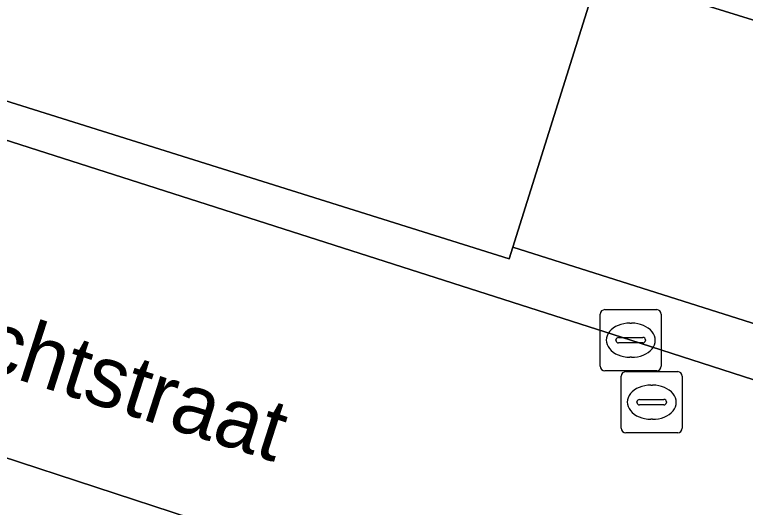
# Model space of a CAD drawing. Extents: x 160675 to 161153, y 383241 to 383714.
# Drawn here: x 160899.69 to 160911.66, y 383397.88 to 383405.95 of the extents above; entities that cross this region are included whole.
import ezdxf

# ---------------------------------------------------------------- set-up
doc = ezdxf.new("R2010")
doc.units = 0
for name, color, linetype in [('IMGEO_Brandkraan', 7, 'Continuous'), ('IMGEO_Groenvoorziening', 7, 'Continuous'), ('IMGEO_Hek', 7, 'Continuous'), ('IMGEO_Kolk', 7, 'Continuous'), ('IMGEO_Openbare_ruimte_label', 7, 'Continuous'), ('IMGEO_Pand', 7, 'Continuous'), ('IMGEO_Parkeervlak_open', 7, 'Continuous'), ('IMGEO_Rijbaan_lokaal_open', 7, 'Continuous'), ('IMGEO_Voetpad_open', 7, 'Continuous')]:
    doc.layers.add(name, color=color, linetype=linetype)

msp = doc.modelspace()

# ---------------------------------------------------------------- linework, layer by layer
at = {"layer": 'IMGEO_Brandkraan'}
for p, q in [((160909.699, 383400.1), (160910.551, 383400.1)), ((160909.624, 383399.174), (160909.624, 383400.026)), ((160910.625, 383400.026), (160910.625, 383399.174)), ((160910.112, 383399.88), (160910.137, 383399.88)), ((160909.883, 383399.594), (160909.883, 383399.606)), ((160909.926, 383399.643), (160910.324, 383399.643)), ((160910.367, 383399.606), (160910.367, 383399.594)), ((160910.321, 383399.557), (160909.923, 383399.557)), ((160910.135, 383399.32), (160910.11, 383399.32)), ((160910.551, 383399.1), (160909.699, 383399.1))]:
    msp.add_line(p, q, dxfattribs=at)
for points in [[(160909.699, 383400.1), (160910.551, 383400.1)], [(160909.624, 383399.174), (160909.624, 383400.026)], [(160910.625, 383400.026), (160910.625, 383399.174)], [(160910.551, 383399.1), (160909.699, 383399.1)]]:
    msp.add_lwpolyline(points, dxfattribs=at)
for centre, radius, start, end in [((160909.701, 383400.024), 0.0765, 91.552, 178.448), ((160909.701, 383400.024), 0.0765, 91.552, 178.448), ((160910.549, 383400.024), 0.0765, 1.552, 88.448), ((160910.549, 383400.024), 0.0765, 1.552, 88.448), ((160909.923, 383399.603), 0.0403, 85.8775, 175.7526), ((160909.92, 383399.593), 0.0366, 178.938, 274.7102), ((160910.324, 383399.6), 0.043, 264.8664, 352.4533), ((160910.328, 383399.605), 0.0386, 1.7309, 96.639), ((160909.701, 383399.176), 0.0765, 181.552, 268.448), ((160909.701, 383399.176), 0.0765, 181.552, 268.448), ((160910.549, 383399.176), 0.0765, 271.552, 358.448), ((160910.549, 383399.176), 0.0765, 271.552, 358.448)]:
    msp.add_arc(centre, radius, start, end, dxfattribs=at)
for centre, major_axis, ratio, start_param, end_param in [((160910.111, 383399.6), (-0.387, 0.002), 0.722429, 4.712389, 7.853982), ((160910.136, 383399.6), (-0.39, 0.002), 0.717154, 1.570796, 4.712389)]:
    msp.add_ellipse(centre, major_axis=major_axis, ratio=ratio, start_param=start_param, end_param=end_param, dxfattribs=at)
at = {"layer": 'IMGEO_Groenvoorziening'}
for points in [[(160900.213, 383446.777), (160898.49, 383441.561), (160894.704, 383430.007), (160895.585, 383429.72), (160894.728, 383427.15), (160893.842, 383427.457), (160889.462, 383413.962), (160887.438, 383407.737), (160890.968, 383406.604), (160893.121, 383405.949), (160909.781, 383400.615), (160922.621, 383396.479), (160938.323, 383391.448), (160946.431, 383388.877)], [(160947.062, 383389.199), (160947.221, 383389.66), (160907.851, 383402.14), (160907.79, 383401.946), (160898.585, 383404.834), (160900.061, 383409.537), (160909.266, 383406.649), (160910.259, 383406.337), (160910.529, 383407.197), (160912.129, 383412.296), (160913.38, 383416.284), (160913.65, 383417.145), (160913.867, 383417.846), (160914.857, 383421.125)]]:
    msp.add_lwpolyline(points, dxfattribs=at)
at = {"layer": 'IMGEO_Hek'}
msp.add_lwpolyline([(160947.221, 383389.66), (160907.851, 383402.14)], dxfattribs=at)
at = {"layer": 'IMGEO_Kolk'}
for p, q in [((160909.28, 383400.189), (160909.28, 383401.041)), ((160909.355, 383401.115), (160910.207, 383401.115)), ((160910.281, 383401.041), (160910.281, 383400.189)), ((160909.768, 383400.895), (160909.793, 383400.895)), ((160909.539, 383400.609), (160909.539, 383400.621)), ((160909.977, 383400.572), (160909.579, 383400.572)), ((160909.582, 383400.658), (160909.98, 383400.658)), ((160910.023, 383400.621), (160910.023, 383400.609)), ((160909.791, 383400.335), (160909.766, 383400.335)), ((160910.207, 383400.115), (160909.355, 383400.115))]:
    msp.add_line(p, q, dxfattribs=at)
for points in [[(160909.28, 383400.189), (160909.28, 383401.041)], [(160909.355, 383401.115), (160910.207, 383401.115)], [(160910.281, 383401.041), (160910.281, 383400.189)], [(160910.207, 383400.115), (160909.355, 383400.115)]]:
    msp.add_lwpolyline(points, dxfattribs=at)
for centre, radius, start, end in [((160909.357, 383401.039), 0.0765, 91.552, 178.448), ((160909.357, 383401.039), 0.0765, 91.552, 178.448), ((160910.205, 383401.039), 0.0765, 1.552, 88.448), ((160910.205, 383401.039), 0.0765, 1.552, 88.448), ((160909.579, 383400.618), 0.0403, 85.8775, 175.7526), ((160909.576, 383400.608), 0.0366, 178.938, 274.7102), ((160909.98, 383400.615), 0.043, 264.8664, 352.4533), ((160909.984, 383400.62), 0.0386, 1.7309, 96.639), ((160909.357, 383400.191), 0.0765, 181.552, 268.448), ((160909.357, 383400.191), 0.0765, 181.552, 268.448), ((160910.205, 383400.191), 0.0765, 271.552, 358.448), ((160910.205, 383400.191), 0.0765, 271.552, 358.448)]:
    msp.add_arc(centre, radius, start, end, dxfattribs=at)
for centre, major_axis, ratio, start_param, end_param in [((160909.767, 383400.615), (-0.387, 0.002), 0.722429, 4.712389, 7.853982), ((160909.792, 383400.615), (-0.39, 0.002), 0.717154, 1.570796, 4.712389)]:
    msp.add_ellipse(centre, major_axis=major_axis, ratio=ratio, start_param=start_param, end_param=end_param, dxfattribs=at)
at = {"layer": 'IMGEO_Pand'}
msp.add_lwpolyline([(160907.79, 383401.946), (160907.851, 383402.14), (160909.266, 383406.649), (160900.061, 383409.537), (160898.585, 383404.834)], close=True, dxfattribs=at)
at = {"layer": 'IMGEO_Parkeervlak_open'}
for points in [[(160910.259, 383406.337), (160909.266, 383406.649), (160907.851, 383402.14), (160947.221, 383389.66), (160950.774, 383388.534), (160952.131, 383392.705), (160952.252, 383393.077)], [(160952.446, 383393.288), (160910.259, 383406.337)]]:
    msp.add_lwpolyline(points, dxfattribs=at)
at = {"layer": 'IMGEO_Rijbaan_lokaal_open'}
for points in [[(160961.834, 383435.436), (160951.457, 383433.034), (160934.63, 383438.001), (160915.704, 383443.719), (160912.495, 383433.743), (160909.469, 383424.262), (160909.234, 383423.484), (160915.017, 383421.657), (160914.857, 383421.125), (160952.366, 383409.411), (160952.452, 383409.683), (160953.022, 383409.495), (160951.411, 383404.407), (160950.007, 383400.003), (160949.472, 383400.175), (160949.567, 383400.481), (160912.129, 383412.296), (160910.529, 383407.197), (160910.259, 383406.337), (160952.446, 383393.288)], [(160922.621, 383396.479), (160909.781, 383400.615), (160893.121, 383405.949), (160890.968, 383406.604), (160887.438, 383407.737), (160879.89, 383410.16)], [(160870.773, 383407.909), (160899.445, 383398.723), (160902.588, 383397.698), (160937.803, 383386.409), (160953.275, 383381.428), (160955.527, 383379.454), (160957.362, 383377.84), (160957.988, 383377.643), (160975.522, 383372.116), (160978.404, 383371.21), (160983.568, 383369.569)]]:
    msp.add_lwpolyline(points, dxfattribs=at)
at = {"layer": 'IMGEO_Voetpad_open'}
msp.add_lwpolyline([(160902.588, 383397.698), (160899.445, 383398.723), (160898.75, 383396.637), (160898.106, 383394.467), (160869.425, 383403.701)], dxfattribs=at)

# ---------------------------------------------------------------- texts
at = {"layer": 'IMGEO_Openbare_ruimte_label'}
msp.add_text('Lichtstraat', height=1, rotation=342.1811, dxfattribs=at).set_placement((160898.073, 383400.507))

doc.saveas('drawing.dxf')
